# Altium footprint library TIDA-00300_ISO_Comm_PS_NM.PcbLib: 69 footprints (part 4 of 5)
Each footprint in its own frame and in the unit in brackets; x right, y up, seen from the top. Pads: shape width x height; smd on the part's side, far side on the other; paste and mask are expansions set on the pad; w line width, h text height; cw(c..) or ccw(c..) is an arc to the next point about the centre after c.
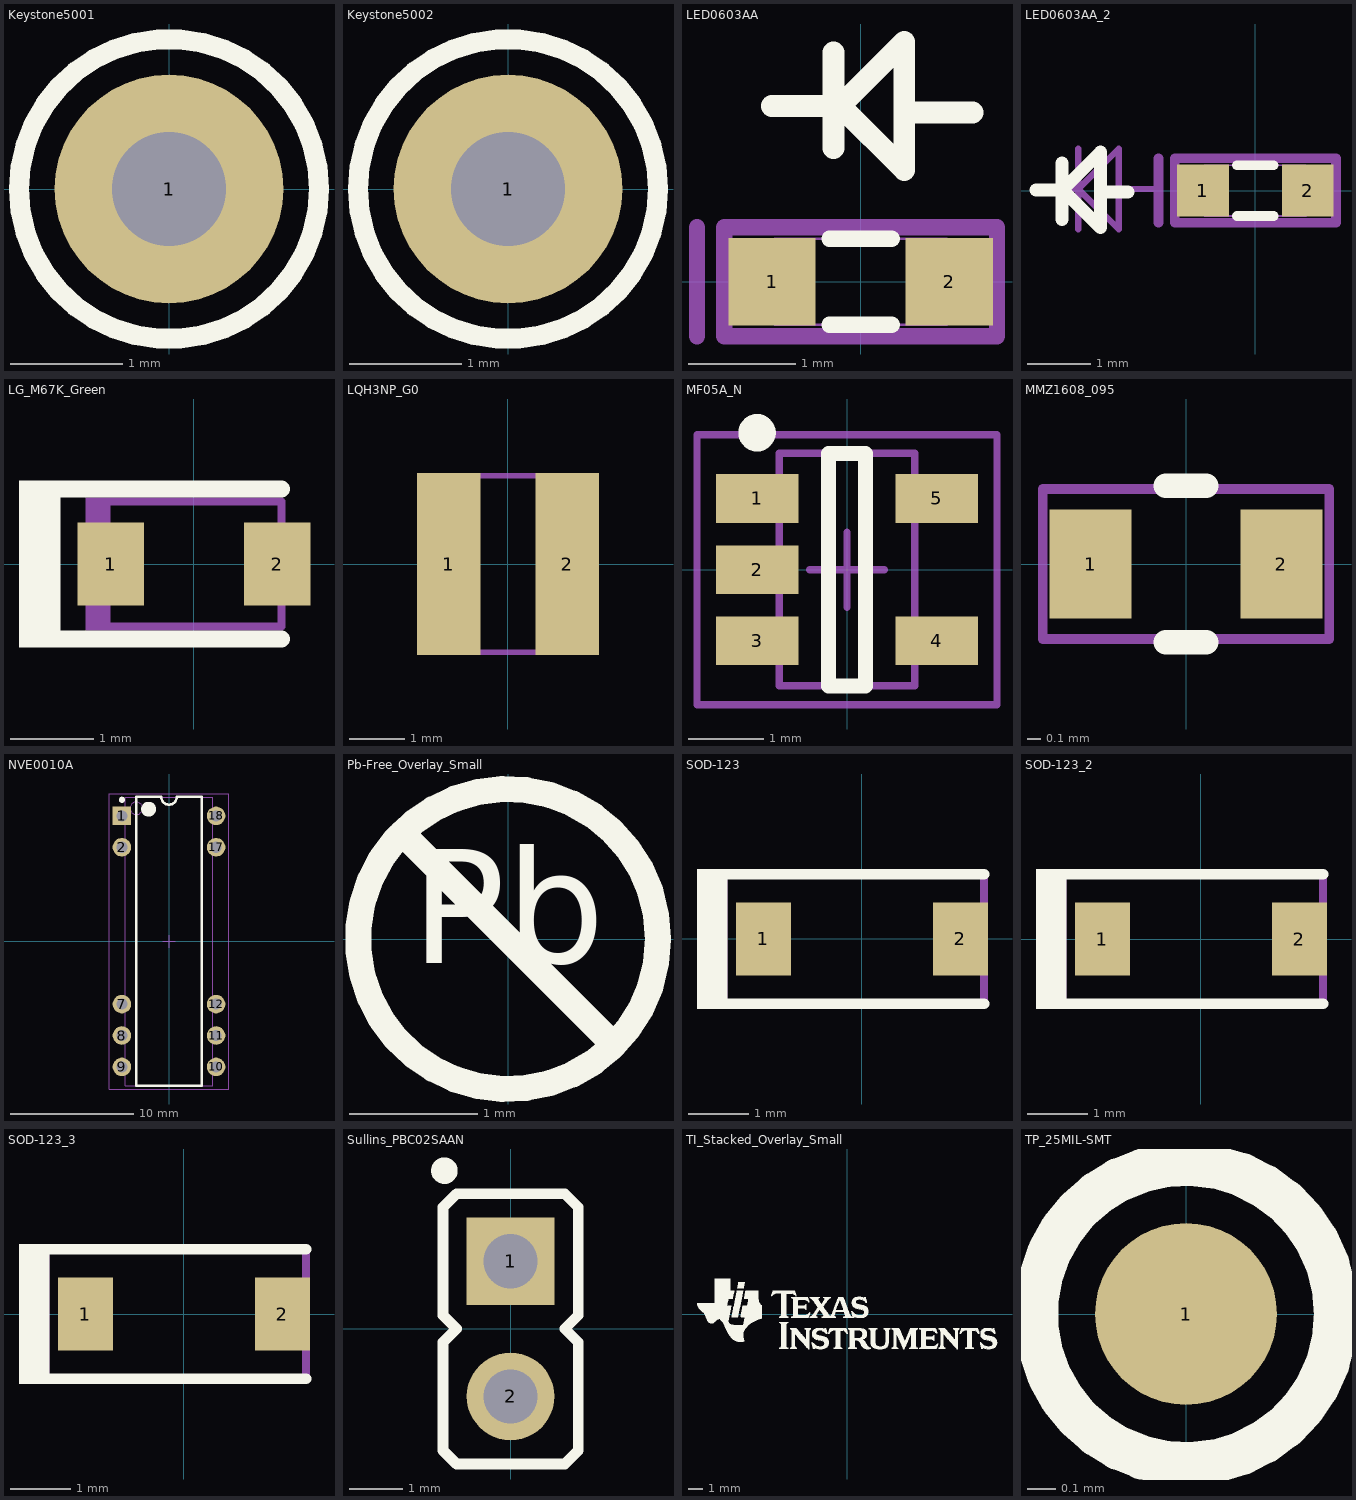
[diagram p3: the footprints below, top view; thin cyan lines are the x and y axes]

## Keystone5001 [mil] "For Keystone 500x miniature loop terminals"
height 181.1
pads (1):
  round 80 hole 40: 1(0,0)
Top Overlay:
  circle w7: c0,0 r52.5
Mechanical 5:
  circle w3.94: c0,0 r52.5
  text ".Designator" at -21,106.86 h20
3D body "Keystone_5001.stp": height 181.97, standoff -118.11, extent -49,-49 49.04,49.24

## Keystone5002 [mil] "For Keystone 500x miniature loop terminals"
height 181.1
pads (1):
  round 80 hole 40: 1(0,0)
Top Overlay:
  circle w7: c0,0 r52.5
Mechanical 5:
  circle w3.94: c0,0 r52.5
  text ".Designator" at -21,108.42 h20
3D body "Keystone_5002.stp": height 181.97, standoff -118.11, extent -49,-49 49.04,49.23

## LED0603AA [mil]
height 118.11
pads (2):
  rect 32x32 smd: 1(-32.48,0) 2(32.48,0)
Top Overlay:
  lines w6: -11.42,-15.75 11.42,-15.75 ; -11.42,15.75 11.42,15.75
  lines w8: -32.58,64.38 -7.58,64.38 16,87.96 16,41 -7.38,64.38 ; -10,49 -10,84 ; 16,62 41,62
Mechanical 5:
  lines w6: -60,-20 -60,20 ; -50,-20 50,-20 50,20 -50,20 -50,-20
  text ".designator" at -25.56,-9 h20
Mechanical 15:
  lines w1: -31.5,-15.75 31.5,-15.75 31.5,15.75 -31.5,15.75 -31.5,-15.75

## LED0603AA_2 [mil]
pads (2):
  rect 32x32 smd: 1(-32.48,0) 2(32.48,0)
Top Overlay:
  lines w6: -11.42,-15.75 11.42,-15.75 ; -11.42,15.75 11.42,15.75
  lines w8: -136,0.38 -119.38,0.38 -96,-23 -96,23.96 -119.58,0.38 ; -120,-18 -120,17 ; -95,-1 -79,-1
Mechanical 5:
  lines w6: -60,-20 -60,20 ; -50,-20 -50,20 50,20 50,-20 -50,-20
  text ".designator" at -26,-10 h20
Mechanical 15:
  lines w1: -31.5,-15.75 -31.5,15.75 31.5,15.75 31.5,-15.75 -31.5,-15.75
  lines w3.94: -134.79,0.96 -109.79,0.96 ; -109.79,-24.04 -109.79,25.96 ; -84.79,0.96 -59.79,0.96 ; -109.79,0.96 -84.79,-24.04 -84.79,25.96 -109.79,0.96

## LG_M67K_Green [mm] "SMD, 2-Leads, Body 2x1.4mm, Pitch 2mm"
height 1.4
pads (2):
  rect 0.8x1 smd mask+0: 1(-1,0) 2(1,0)
Top Overlay:
  rectangle: -2.1,-1 -1.6,1
  lines w0.2: -2,-0.9 1.05,-0.9 ; -2,0.9 1.05,0.9
Mechanical 5:
  rectangle: -1.3,-0.8 -1.05,0.8
  lines w0.1: -1.05,-0.75 -1.05,0.75 1.05,0.75 1.05,-0.75 -1.05,-0.75
  text ".Designator" at -0.425,-0.279 h0.51
3D body: height 0.9, standoff 0.6, extent -0.799,-0.149 -0.6,0.15
3D body: height 1.4, standoff 0, extent -1.049,-0.749 1.049,0.749

## LQH3NP_G0 [mm] "MURATA"
height 1
pads (2):
  rect 1.15x3.3 smd: 1(-1.075,0) 2(1.075,0)
Mechanical 5:
  circle w0.08: c-1.124,0.4 r0.224
  lines w0.1: -1.6,-1.6 -1.6,1.6 1.6,1.6 1.6,-1.6 -1.6,-1.6
  text ".Designator" at -0.229,0.457 h0.51
3D body: height 1, standoff 0, extent -1.599,-1.599 1.599,1.599
3D body: height 1.01, standoff 0.5, extent -1.383,0.177 -0.937,0.623

## MF05A_N [mm] "SOT23, 5-Leads, Body 2.9x1.6mm, Pitch 0.95mm, Lead Span 2.8mm, IPC Medium Density"
height 1.19
pads (5):
  rect 1.1x0.65 smd: 1(-1.2,0.95) 2(-1.2,0) 3(-1.2,-0.95) 4(1.2,-0.95) 5(1.2,0.95)
Top Overlay:
  circle w0.25: c-1.2,1.825 r0.125
  lines w0.2: -0.25,-1.55 -0.25,1.55 0.25,1.55 0.25,-1.55 -0.25,-1.55
Mechanical 5:
  circle w0.152: c-1.397,0.889 r0.127
  lines w0.1: -0.9,-1.55 -0.9,1.55 0.9,1.55 0.9,-1.55 -0.9,-1.55
  text ".Designator" at 0.187,-0.762 h0.51
Mechanical 13:
  lines w0.1: -0.9,-1.55 0.9,-1.55 0.9,1.55 -0.9,1.55 -0.9,-1.55
Mechanical 15:
  lines w0.1: -0.5,0 0.5,0 ; 0,-0.5 0,0.5 ; -2,-1.8 2,-1.8 2,1.8 -2,1.8 -2,-1.8
3D body: height 1.19, standoff 0, extent -0.9,-1.55 0.9,1.55

## MMZ1608_095 [mm] "TDK"
height 0.95
pads (2):
  rect 0.6x0.8 smd: 1(-0.7,0) 2(0.7,0)
Top Overlay:
  lines w0.18: -0.15,-0.575 0.15,-0.575 ; -0.15,0.575 0.15,0.575
Mechanical 5:
  lines w0.07: -1.05,-0.55 1.05,-0.55 1.05,0.55 -1.05,0.55 -1.05,-0.55
  text ".Designator" at 0.468,0.201 h0.51
3D body: height 0.95, standoff 0, extent 0.501,-0.474 0.874,0.474
3D body: height 0.95, standoff 0, extent -0.499,-0.474 0.499,0.474
3D body: height 0.95, standoff 0, extent -0.874,-0.474 -0.501,0.474

## NVE0010A [mm] "DIP, 10-Leads, Body 22.86x6.61mm, Pitch 2.54mm"
height 5.33
pads (10):
  rect 1.5x1.5 hole 0.9: 1(-3.81,10.16)
  round 1.5 hole 0.9: 2(-3.81,7.62) 7(-3.81,-5.08) 8(-3.81,-7.62) 9(-3.81,-10.16) 10(3.81,-10.16) 11(3.81,-7.62) 12(3.81,-5.08) 17(3.81,7.62) 18(3.81,10.16)
Top Overlay:
  circle w0.6: c-1.65,10.7 r0.3
  circle w0.25: c-3.81,11.46 r0.125
  lines w0.2: -2.65,-11.7 2.65,-11.7 2.65,11.7 0.635,11.7 cw(c0,11.7) -0.635,11.7 -2.65,11.7 -2.65,-11.7
Mechanical 5:
  circle w0.1: c-2.65,10.775 r0.5
  lines w0.1: -3.55,-11.675 3.55,-11.675 3.55,11.675 -3.55,11.675 -3.55,-11.675
  text ".Designator" at -0.127,0.406 h0.51
Mechanical 15:
  lines w0.05: -4.85,-11.95 4.85,-11.95 4.85,11.95 -4.85,11.95 -4.85,-11.95
  lines w0.1: -0.5,0 0.5,0 ; 0,-0.5 0,0.5
3D body: height 5.33, standoff 0.38, extent -3.55,-11.675 3.55,11.675
3D body: height 0, standoff -1.6, extent 3.675,9.8 3.945,10.52
3D body: height 2.99, standoff 2.72, extent 3.55,9.66 3.945,10.66
3D body: height 2.72, standoff 0, extent 3.675,9.66 3.945,10.66
3D body: height 0, standoff -1.6, extent 3.675,7.26 3.945,7.98
3D body: height 2.99, standoff 2.72, extent 3.55,7.12 3.945,8.12
3D body: height 2.72, standoff 0, extent 3.675,7.12 3.945,8.12
3D body: height 0, standoff -1.6, extent 3.675,-5.44 3.945,-4.72
3D body: height 2.99, standoff 2.72, extent 3.55,-5.58 3.945,-4.58
3D body: height 2.72, standoff 0, extent 3.675,-5.58 3.945,-4.58
3D body: height 0, standoff -1.6, extent 3.675,-7.98 3.945,-7.26
3D body: height 2.99, standoff 2.72, extent 3.55,-8.12 3.945,-7.12
3D body: height 2.72, standoff 0, extent 3.675,-8.12 3.945,-7.12
3D body: height 0, standoff -1.6, extent 3.675,-10.52 3.945,-9.8
3D body: height 2.99, standoff 2.72, extent 3.55,-10.66 3.945,-9.66
3D body: height 2.72, standoff 0, extent 3.675,-10.66 3.945,-9.66
3D body: height 0, standoff -1.6, extent -3.945,-10.52 -3.675,-9.8
3D body: height 2.99, standoff 2.72, extent -3.945,-10.66 -3.55,-9.66
3D body: height 2.72, standoff 0, extent -3.945,-10.66 -3.675,-9.66
3D body: height 0, standoff -1.6, extent -3.945,-7.98 -3.675,-7.26
3D body: height 2.99, standoff 2.72, extent -3.945,-8.12 -3.55,-7.12
3D body: height 2.72, standoff 0, extent -3.945,-8.12 -3.675,-7.12
3D body: height 0, standoff -1.6, extent -3.945,-5.44 -3.675,-4.72
3D body: height 2.99, standoff 2.72, extent -3.945,-5.58 -3.55,-4.58
3D body: height 2.72, standoff 0, extent -3.945,-5.58 -3.675,-4.58
3D body: height 0, standoff -1.6, extent -3.945,7.26 -3.675,7.98
3D body: height 2.99, standoff 2.72, extent -3.945,7.12 -3.55,8.12
3D body: height 2.72, standoff 0, extent -3.945,7.12 -3.675,8.12
3D body: height 0, standoff -1.6, extent -3.945,9.8 -3.675,10.52
3D body: height 2.99, standoff 2.72, extent -3.945,9.66 -3.55,10.66
3D body: height 2.72, standoff 0, extent -3.945,9.66 -3.675,10.66

## Pb-Free_Overlay_Small [mm]
height 7.6
Top Overlay:
  circle w0.203: c0,0 r1.168
  lines w0.203: -0.826,0.826 0.826,-0.826
  text "Pb" at -0.752,-0.48 h1.52

## SOD-123 [mm] "On Semi recommended land pattern"
height 1.35
pads (2):
  rect 0.915x1.22 smd: 1(-1.637,0) 2(1.637,0)
Top Overlay:
  rectangle: -2.743,-1.168 -2.235,1.168
  lines w0.178: -2.413,-1.079 2.032,-1.079 ; -2.413,1.079 2.032,1.079
Mechanical 5:
  rectangle: -2.743,-1.168 -2.235,1.168
  lines w0.127: -2.413,-1.079 2.032,-1.079 2.032,1.079 -2.413,1.079
  text ".Designator" at -0.254,-0.711 h0.51
3D body "SOD-123.stp": height 1.35, standoff 0, extent -1.932,-0.9 1.932,0.9

## SOD-123_2 [mm]
pads (2):
  rect 0.915x1.22 smd: 1(-1.637,0) 2(1.637,0)
Top Overlay:
  rectangle: -2.743,-1.168 -2.235,1.169
  lines w0.178: -2.413,-1.079 2.032,-1.079 ; -2.413,1.079 2.032,1.079
Mechanical 5:
  rectangle: -2.743,-1.168 -2.235,1.169
  lines w0.127: -2.413,-1.079 2.032,-1.079 2.032,1.079 -2.413,1.079
  text ".Designator" at -1.956,-0.33 h0.51
3D body "SOD-123.stp": height 1.35, standoff 0, extent -1.932,-0.9 1.932,0.9

## SOD-123_3 [mm]
pads (2):
  rect 0.915x1.22 smd: 1(-1.637,0) 2(1.637,0)
Top Overlay:
  rectangle: -2.743,-1.168 -2.235,1.168
  lines w0.178: -2.413,-1.079 2.032,-1.079 ; -2.413,1.079 2.032,1.079
Mechanical 5:
  rectangle: -2.743,-1.168 -2.235,1.168
  lines w0.127: -2.413,-1.079 2.032,-1.079 2.032,1.079 -2.413,1.079
  text ".Designator" at 0.197,0.181 h0.51
3D body "SOD-123.stp": height 1.35, standoff 0, extent -1.932,-0.9 1.932,0.9

## Sullins_PBC02SAAN [mm] "Sullins 100mil, 1x2, 230 mil above insulator"
height 8.382
pads (2):
  rect 1.65x1.65 hole 1.016: 1(0,1.27)
  round 1.65 hole 1.016: 2(0,-1.27)
Top Overlay:
  circle w0.25: c-1.245,2.972 r0.125
  lines w0.2: -1.27,-2.286 -1.016,-2.54 1.016,-2.54 1.27,-2.286 1.27,-0.254 1.016,0 1.27,0.254 1.27,2.286 1.016,2.54 -1.016,2.54 -1.27,2.286 -1.27,0.254 -1.016,0 -1.27,-0.254 -1.27,-2.286
Mechanical 5:
  lines w0.1: -1.27,-2.286 -1.27,-0.254 -1.016,0 -1.27,0.254 -1.27,2.286 -1.016,2.54 1.016,2.54 1.27,2.286 1.27,0.254 1.016,0 1.27,-0.254 1.27,-2.286 1.016,-2.54 -1.016,-2.54 -1.27,-2.286
  text ".Designator" at -0.33,-0.305 h0.51
3D body: height 8.38, standoff -3.05, extent -0.317,0.953 0.317,1.587
3D body: height 8.38, standoff -3.05, extent -0.317,-1.587 0.317,-0.953
3D body: height 2.54, standoff 0, extent -1.27,-2.54 1.27,2.54

## TI_Stacked_Overlay_Small [mm]
Top Overlay:
  drawing of 18 lines, arcs and shapes, not listed

## TP_25MIL-SMT [mm]
height 7.6
pads (1):
  round 0.635 smd mask-0.064: 1(0,0)
Top Overlay:
  circle w0.152: c0,0 r0.524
